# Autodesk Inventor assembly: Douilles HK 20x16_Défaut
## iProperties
Shininess: 64.0
Length Units: 11269
Angle Units: 11279
Time Units: 11290
Mass Units: 11283
Length Display Precision: 3
Angle Display Precision: 2
Compacted: True
Created: 2006-01
Part Number: Douilles HK 20x16_Défaut
Document SubType Name: Assembly
Designer: riri
Density: 0.0
Volumn: 0.0
Area: 0.0
PropertySet Name: Model Information
Control State: 0
Master: False
Checked Out: False
Author: riri
